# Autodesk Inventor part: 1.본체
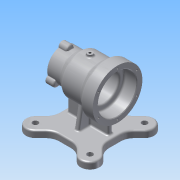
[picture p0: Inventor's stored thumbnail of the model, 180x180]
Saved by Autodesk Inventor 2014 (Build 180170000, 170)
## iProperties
Created: 2017-03
Part Number: 1.본체
Material: 알루미늄 6061
Document SubType Name: Modeling
Designer: 00
Density: 2.71 g/cm^3
Appearance: 알루미늄 - 평지
Author: 00
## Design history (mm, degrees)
sketch "스케치2"
  geometry: L1 (-20.958, 45)-(20.958, 45); L2 (-45, -20.958)-(-45, 20.958); L3 (0, 0)-(98.995, 0); L4 (-37.477, 61.518)-(-20.958, 45); L5 (-61.518, 37.477)-(-45, 20.958); L6 (-61.518, -37.477)-(-45, -20.958); L7 (-37.477, -61.518)-(-20.958, -45); L8 (37.477, -61.518)-(20.958, -45); L9 (61.518, -37.477)-(45, -20.958); L10 (61.518, 37.477)-(45, 20.958); L11 (37.477, 61.518)-(20.958, 45); L12 (45, 20.958)-(45, -20.958); L13 (20.958, -45)-(-20.958, -45); A1 r 17 centre (-49.497, 49.497) between (-37.477, 61.518) and (-61.518, 37.477); A2 r 17 centre (-49.497, -49.497) between (-61.518, -37.477) and (-37.477, -61.518); A3 r 17 centre (49.497, -49.497) between (37.477, -61.518) and (61.518, -37.477); A4 r 17 centre (49.497, 49.497) between (61.518, 37.477) and (37.477, 61.518); 2 further points
  constraints: 26 end point, 8 point on circle, 4 centre point, 3 horizontal, 3 tangent, 2 coincident, 1 parallel, 1 vertical, 33 other
  dimensions: "d19" = 34 diameter of A1; "d22" = 360 deg dimension on point (0, 0) A1.centre (derived); "d24" = 45 deg angle of L10 L3; "d25" = 45 distance between parallel lines of L3 L1; "d26" = 53 distance from line of L3.end L10; "d28" = 37.47666 distance from line of L10.start L3
extrude "돌출1" new body sketch "스케치2" distance "d29" = 12; taper "d30" = 0 deg
fillet "모깎기1" dims "d31" = 25
sketch "스케치3"
  geometry: L1 (-45, 0)-(-45, 12) reference; L2 (-45, 12)-(45, 12) reference; L3 (45, 12)-(45, 0) reference; L4 (45, 0)-(-45, 0) reference; L5 (50, 82)-(-50, 82); L6 (-50, 82)-(-50, 127); L7 (-50, 127)-(-30, 127); L8 (-30, 127)-(-19, 118); L9 (-19, 118)-(15, 118); L10 (15, 118)-(27, 109.5); L11 (27, 109.5)-(50, 109.5); L12 (50, 109.5)-(50, 82); 1 further point
  constraints: 16 end point, 4 horizontal, 2 vertical
  dimensions: "d34" = 45 distance of L5.end L6.end; "d35" = 20 distance of L6.end L7.end; "d36" = 31 horizontal distance of L8.end L6.end; "d37" = 72 diameter of L8.end L5; "d38" = 65 horizontal distance of L9.end L6.end; "d39" = 55 diameter of L10.end L5; "d40" = 23 distance of L11.end L10.end; "d74" = 100 horizontal distance of L11.end L6.end; "d75" = 95 distance between parallel lines of L1 L12; "d76" = 109.5 distance between parallel lines of L4 L11
revolve "회전1" sketch "스케치3" stored, may be unused: angle "d45" = 90 deg
sketch "스케치5"
  geometry: A1 r 27.5 centre (0, 0) between (26.609, -6.943) and (26.609, 6.943) reference; A2 r 7 centre (27.5, 0) between (26.609, -6.943) and (26.609, 6.943); A3 r 7 centre (-13.75, 23.816) between (-7.292, 26.516) and (-19.317, 19.573); A4 r 7 centre (-13.75, -23.816) between (-19.317, -19.573) and (-7.292, -26.516); A5 r 27.5 centre (0, 0) between (26.609, -6.943) and (26.609, 6.943); A6 r 27.5 centre (0, 0) between (-7.292, 26.516) and (-19.317, 19.573); A7 r 27.5 centre (0, 0) between (-19.317, -19.573) and (-7.292, -26.516); 1 further point
  constraints: 15 point on circle, 6 centre point, 1 coincident, 13 other
  dimensions: "d57" = 14 diameter of A2; "d60" = 360 deg dimension on A1.centre A2.centre (derived); "d62" = 109.5 distance of point (-82, 0) A2.centre
extrude "돌출2" join sketch "스케치5" distance "d63" = 15; taper "d64" = 0 deg
sketch "스케치6"
  geometry: C1 r 45 at (0, 0) reference; C2 r 35 at (0, 0); 1 further point
  constraints: 1 centre point, 1 coincident
  dimensions: "d65" = 70 diameter of C2
extrude "돌출3" cut sketch "스케치6" distance "d66" = 23; taper "d67" = 0 deg
sketch "스케치7"
  geometry: C1 r 35 at (0, 0) reference; C2 r 26 at (0, 0); 1 further point
  constraints: 1 centre point, 1 coincident
  dimensions: "d68" = 52 diameter of C2
extrude "돌출4" cut sketch "스케치7" distance "d69" = 47; taper "d70" = 0 deg
sketch "스케치8"
  geometry: C1 r 26 at (0, 0) reference; C2 r 17.5 at (0, 0); 1 further point
  constraints: 1 centre point, 1 coincident
  dimensions: "d71" = 35 diameter of C2
extrude "돌출5" cut sketch "스케치8" distance "d72" = 30; taper "d73" = 0 deg
sketch "스케치9"
  geometry: 2 further points
hole "구멍1" sketch "스케치9" at (-40, 0) diameter "d78" = 3.242; stored, may be unused: countersink angle "d82" = 90 deg, drill point angle "d84" = 118 deg; dims "d79" = 9, "d80" = 4, "d81" = 2, "d83" = 11
sketch "스케치10"
  geometry: A1 r 7 centre (0, 0) between (-0.891, -6.943) and (-0.891, 6.943) reference; 2 further points
  constraints: 1 coincident
hole "구멍2" sketch "스케치10" at (0, 0) diameter "d90" = 3.242; stored, may be unused: countersink angle "d94" = 90 deg, drill point angle "d96" = 118 deg; dims "d91" = 9, "d92" = 4, "d93" = 2, "d95" = 11
sketch "스케치11"
  geometry: L1 (45, 12)-(45, 0) reference; L2 (45, 0)-(-45, 0) reference; L3 (-45, 0)-(-45, 12) reference; L4 (-45, 12)-(45, 12) reference; L5 (0, 12)-(25, 12); L6 (25, 12)-(17.242, 56); L7 (17.242, 56)-(0, 48.168); L8 (-17.242, 56)-(0, 48.168); L9 (-25, 12)-(-17.242, 56); L10 (0, 12)-(-25, 12); C1 r 26 at (0, 82) reference; C2 r 36 at (0, 82) reference; 1 further point
  constraints: 12 end point, 1 midpoint, 1 point on line
  dimensions: "d100" = 25 distance of L5.start L5.end; "d101" = 80 deg angle of L6 L5; "d102" = 65.571 deg angle of L1 L7; "d103" = 114.429 deg angle of L1 L8; "d104" = 90 deg angle of L1 L10; "d107" = 14.31992 distance from line of L1.start L8; "d109" = 80 deg angle of L2 L9; "d110" = 51.54078 distance from line of L1.start L7; "d168" = 25 distance of L5.start L9.start
extrude "돌출6" join sketch "스케치11" stored distance "d111" = 8; taper "d112" = 0 deg
sketch "스케치12"
  geometry: L1 (35, 116.5)-(50, 116.5) reference; L2 (50, 116.5)-(50, 111.121) reference; L3 (50, 111.121)-(39, 111.121) reference; L4 (39, 111.121)-(38.026, 109.5) reference; L5 (38.026, 109.5)-(39, 107.879) reference; L6 (39, 107.879)-(50, 107.879) reference; L7 (50, 107.879)-(50, 99.5) reference; L8 (50, 99.5)-(20, 99.5) reference; L9 (20, 99.5)-(20, 108) reference; L10 (20, 108)-(-27, 108) reference; L11 (-27, 108)-(-27, 117) reference; L12 (-27, 117)-(-50, 117) reference; L13 (-50, 117)-(-50, 120.379) reference; L14 (-50, 120.379)-(-39, 120.379) reference; L15 (-39, 120.379)-(-38.026, 122) reference; L16 (-38.026, 122)-(-39, 123.621) reference; L17 (-39, 123.621)-(-50, 123.621) reference; L18 (-50, 123.621)-(-50, 127) reference; L19 (-50, 127)-(-30, 127) reference; L20 (-30, 127)-(-19, 118) reference; L21 (-19, 118)-(15, 118) reference; L22 (15, 118)-(27, 109.5) reference; L23 (27, 109.5)-(35, 109.5) reference; L24 (35, 109.5)-(35, 116.5) reference; L25 (-45, 0)-(-45, 12) reference; L26 (-45, 12)-(-4, 12) reference; L27 (-4, 12)-(-4, 46) reference; L28 (-4, 46)-(-19, 46) reference; L29 (-19, 46)-(-30, 37) reference; L30 (-30, 37)-(-50, 37) reference; L31 (-50, 37)-(-50, 40.379) reference; L32 (-50, 40.379)-(-39, 40.379) reference; L33 (-39, 40.379)-(-38.026, 42) reference; L34 (-38.026, 42)-(-39, 43.621) reference; L35 (-39, 43.621)-(-50, 43.621) reference; L36 (-50, 43.621)-(-50, 47) reference; L37 (-50, 47)-(-27, 47) reference; L38 (-27, 47)-(-27, 56) reference; L39 (-27, 56)-(20, 56) reference; L40 (20, 56)-(20, 64.5) reference; L41 (20, 64.5)-(50, 64.5) reference; L42 (50, 64.5)-(50, 54.5) reference; L43 (50, 54.5)-(27, 54.5) reference; L44 (27, 54.5)-(15, 46) reference; L45 (15, 46)-(4, 46) reference; L46 (4, 46)-(4, 12) reference; L47 (4, 12)-(45, 12) reference; L48 (45, 12)-(45, 0) reference; L49 (45, 0)-(-45, 0) reference; L50 (0, 12)-(-37, 12); L51 (-37, 12)-(-37, 40.379); L52 (-37, 40.379)-(-14.466, 50.25); L53 (-14.466, 50.25)-(0, 50.25); L54 (0, 12)-(37, 12); L55 (37, 12)-(37, 59.5); L56 (37, 59.5)-(21, 54.5); L57 (21, 54.5)-(13.927, 50.25); L58 (13.927, 50.25)-(0, 50.25); 1 further point
  constraints: 18 end point, 2 horizontal, 2 point on line, 2 vertical, 1 perpendicular
  dimensions: "d114" = 37 distance of L50.start L50.end; "d115" = 37 distance of L50.start L54.end; "d116" = 107.354 deg angle of L2 L56; "d117" = 113.655 deg angle of L2 L52; "d118" = 59 deg angle of L4 L54; "d119" = 13 distance between parallel lines of L2 L55; "d120" = 60.871 distance between parallel lines of L3 L53; "d121" = 50.52778 distance from line of L1.end L56; "d122" = 38.20827 distance from line of L1.end L57; "d123" = 34.81738 distance from line of L1.end L52; "d124" = 50 distance from line of L53.end L2
extrude "돌출7" join sketch "스케치12" stored distance "d125" = 8; taper "d126" = 0 deg
sketch "스케치13"
  geometry: C1 r 5 at (-49.497, 49.497); C2 r 5 at (49.497, 49.497); C3 r 5 at (-49.497, -49.497); C4 r 5 at (49.497, -49.497); A1 r 17 centre (-49.497, -49.497) between (-61.518, -37.477) and (-37.477, -61.518) reference; A2 r 17 centre (49.497, -49.497) between (37.477, -61.518) and (61.518, -37.477) reference; A3 r 17 centre (49.497, 49.497) between (61.518, 37.477) and (37.477, 61.518) reference; A4 r 17 centre (-49.497, 49.497) between (-37.477, 61.518) and (-61.518, 37.477) reference; 1 further point
  constraints: 4 centre point, 4 coincident
  dimensions: "d127" = 10 diameter of C1; "d128" = 10 diameter of C2; "d129" = 10 diameter of C3; "d130" = 10 diameter of C4
extrude "돌출8" cut sketch "스케치13" distance "d131" = 12; taper "d132" = 0 deg
fillet "모깎기2" dims "d133" = 3
fillet "모깎기3" dims "d134" = 3
fillet "모깎기4" dims "d135" = 3
fillet "모깎기5" dims "d136" = 1
fillet "모깎기7" dims "d138" = 3
fillet "모깎기8" dims "d139" = 1
fillet "모깎기9" dims "d140" = 3
chamfer "모따기1" distance "d141" = 1; stored, may be unused: second distance "d142" = 2, angle "d143" = 45 deg
chamfer "모따기2" distance "d144" = 1; stored, may be unused: second distance "d145" = 2, angle "d146" = 45 deg
fillet "모깎기10" dims "d147" = 3
fillet "모깎기11" dims "d148" = 3
node "작업 평면1"
sketch "스케치16"
  geometry: L1 (39, 1.621)-(38.026, 0) reference; L2 (38.026, 0)-(39, -1.621) reference; L3 (39, -1.621)-(50, -1.621) reference; L4 (50, -1.621)-(50, -20.616) reference; L5 (50, -20.616)-(31, -20.616) reference; L6 (31, 20.616)-(50, 20.616) reference; L7 (50, 20.616)-(50, 1.621) reference; L8 (50, 1.621)-(39, 1.621) reference; C1 r 5 at (0, 0); 3 further points
  constraints: 1 centre point, 1 coincident, 1 vertical alignment, 2 other
  dimensions: "d151" = 10 diameter of C1
extrude "돌출9" join sketch "스케치16" stored distance "d152" = 10; taper "d153" = 0 deg
hole "구멍3" diameter "d156" = 4.134; stored, may be unused: countersink angle "d160" = 82 deg, drill point angle "d162" = 0 deg; dims "d154" = 10, "d155" = 10, "d157" = 14, "d158" = 3.023, "d159" = 2, "d161" = 14
fillet "모깎기12" dims "d163" = 3
sketch "스케치18"
  geometry: L1 (-42, 10.603)-(-42, -10.603) reference; L2 (-59.397, 39.598)-(-50.201, 30.402) reference; L3 (-30.402, 50.201)-(-39.598, 59.397) reference; L4 (10.603, 42)-(-10.603, 42) reference; L5 (39.598, 59.397)-(30.402, 50.201) reference; L6 (50.201, 30.402)-(59.397, 39.598) reference; L7 (42, -10.603)-(42, 10.603) reference; L8 (59.397, -39.598)-(50.201, -30.402) reference; L9 (30.402, -50.201)-(39.598, -59.397) reference; L10 (-10.603, -42)-(10.603, -42) reference; L11 (-39.598, -59.397)-(-30.402, -50.201) reference; L12 (-50.201, -30.402)-(-59.397, -39.598) reference; L13 (7, -21.425)-(7, -7) reference; L14 (7, -7)-(34, -7) reference; L15 (40, -1)-(40, 1) reference; L16 (34, 7)-(7, 7) reference; L17 (7, 7)-(7, 21.425) reference; L18 (1, 27.517)-(-1, 27.517) reference; L19 (-7, 21.425)-(-7, 7) reference; L20 (-7, 7)-(-34, 7) reference; L21 (-40, 1)-(-40, -1) reference; L22 (-34, -7)-(-7, -7) reference; L23 (-7, -7)-(-7, -21.425) reference; L24 (-1, -27.517)-(1, -27.517) reference; L25 (-45, 10.603)-(-45, -10.603) reference; C1 r 5 at (-49.497, -49.497) reference; C2 r 5 at (-49.497, 49.497) reference; C3 r 5 at (49.497, 49.497) reference; C4 r 5 at (49.497, -49.497) reference; A1 r 28 centre (-70, -10.603) between (-50.201, -30.402) and (-42, -10.603) reference; A2 r 28 centre (-70, 10.603) between (-42, 10.603) and (-50.201, 30.402) reference; A3 r 14 centre (-49.497, 49.497) between (-39.598, 59.397) and (-59.397, 39.598) reference; A4 r 28 centre (-10.603, 70) between (-30.402, 50.201) and (-10.603, 42) reference; A5 r 28 centre (10.603, 70) between (10.603, 42) and (30.402, 50.201) reference; A6 r 14 centre (49.497, 49.497) between (59.397, 39.598) and (39.598, 59.397) reference; A7 r 28 centre (70, 10.603) between (50.201, 30.402) and (42, 10.603) reference; A8 r 28 centre (70, -10.603) between (42, -10.603) and (50.201, -30.402) reference; A9 r 14 centre (49.497, -49.497) between (39.598, -59.397) and (59.397, -39.598) reference; A10 r 28 centre (10.603, -70) between (30.402, -50.201) and (10.603, -42) reference; A11 r 28 centre (-10.603, -70) between (-10.603, -42) and (-30.402, -50.201) reference; A12 r 14 centre (-49.497, -49.497) between (-59.397, -39.598) and (-39.598, -59.397) reference; A13 r 6 centre (34, -1) between (34, -7) and (40, -1) reference; A14 r 6 centre (34, 1) between (40, 1) and (34, 7) reference; A15 r 6 centre (-34, 1) between (-34, 7) and (-40, 1) reference; A16 r 6 centre (-34, -1) between (-40, -1) and (-34, -7) reference; 2 further points
  constraints: 5 other
  dimensions: "d164" = 35 distance of point (0, 0) point (0, 35); "d165" = 45 distance from line of L25 point (0, 35)
feature "엠보싱1" sketch "스케치18" dims "d19" = 34, "d22" = 360 deg (derived), "d24" = 45 deg, "d25" = 45, "d26" = 53, "d28" = 37.47666, "d166" = 0.5, "d167" = 0
node "솔리드1"
pattern_circular "원형 패턴1" dims angle "d86" = 360 deg
pattern_circular "원형 패턴2" dims angle "d98" = 360 deg
node "절단 모서리 투영1"
node "절단 모서리 투영3"
node "절단 모서리 투영4"
node "절단 모서리 투영7"
node "절단 모서리 투영9"
other parameters: "d150" = 122
